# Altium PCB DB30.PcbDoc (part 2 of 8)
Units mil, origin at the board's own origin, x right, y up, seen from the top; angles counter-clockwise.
Board outline 3236.22 x 4456.69 mil, 8 copper layers (Top Layer, MidLayer1, MidLayer2, GND-Layer5, MidLayer3, VCC, MidLayer4, Bottom Layer), stack 61.8 mil thick; 219 components, 472 nets, 1811 pads, 1561 vias.
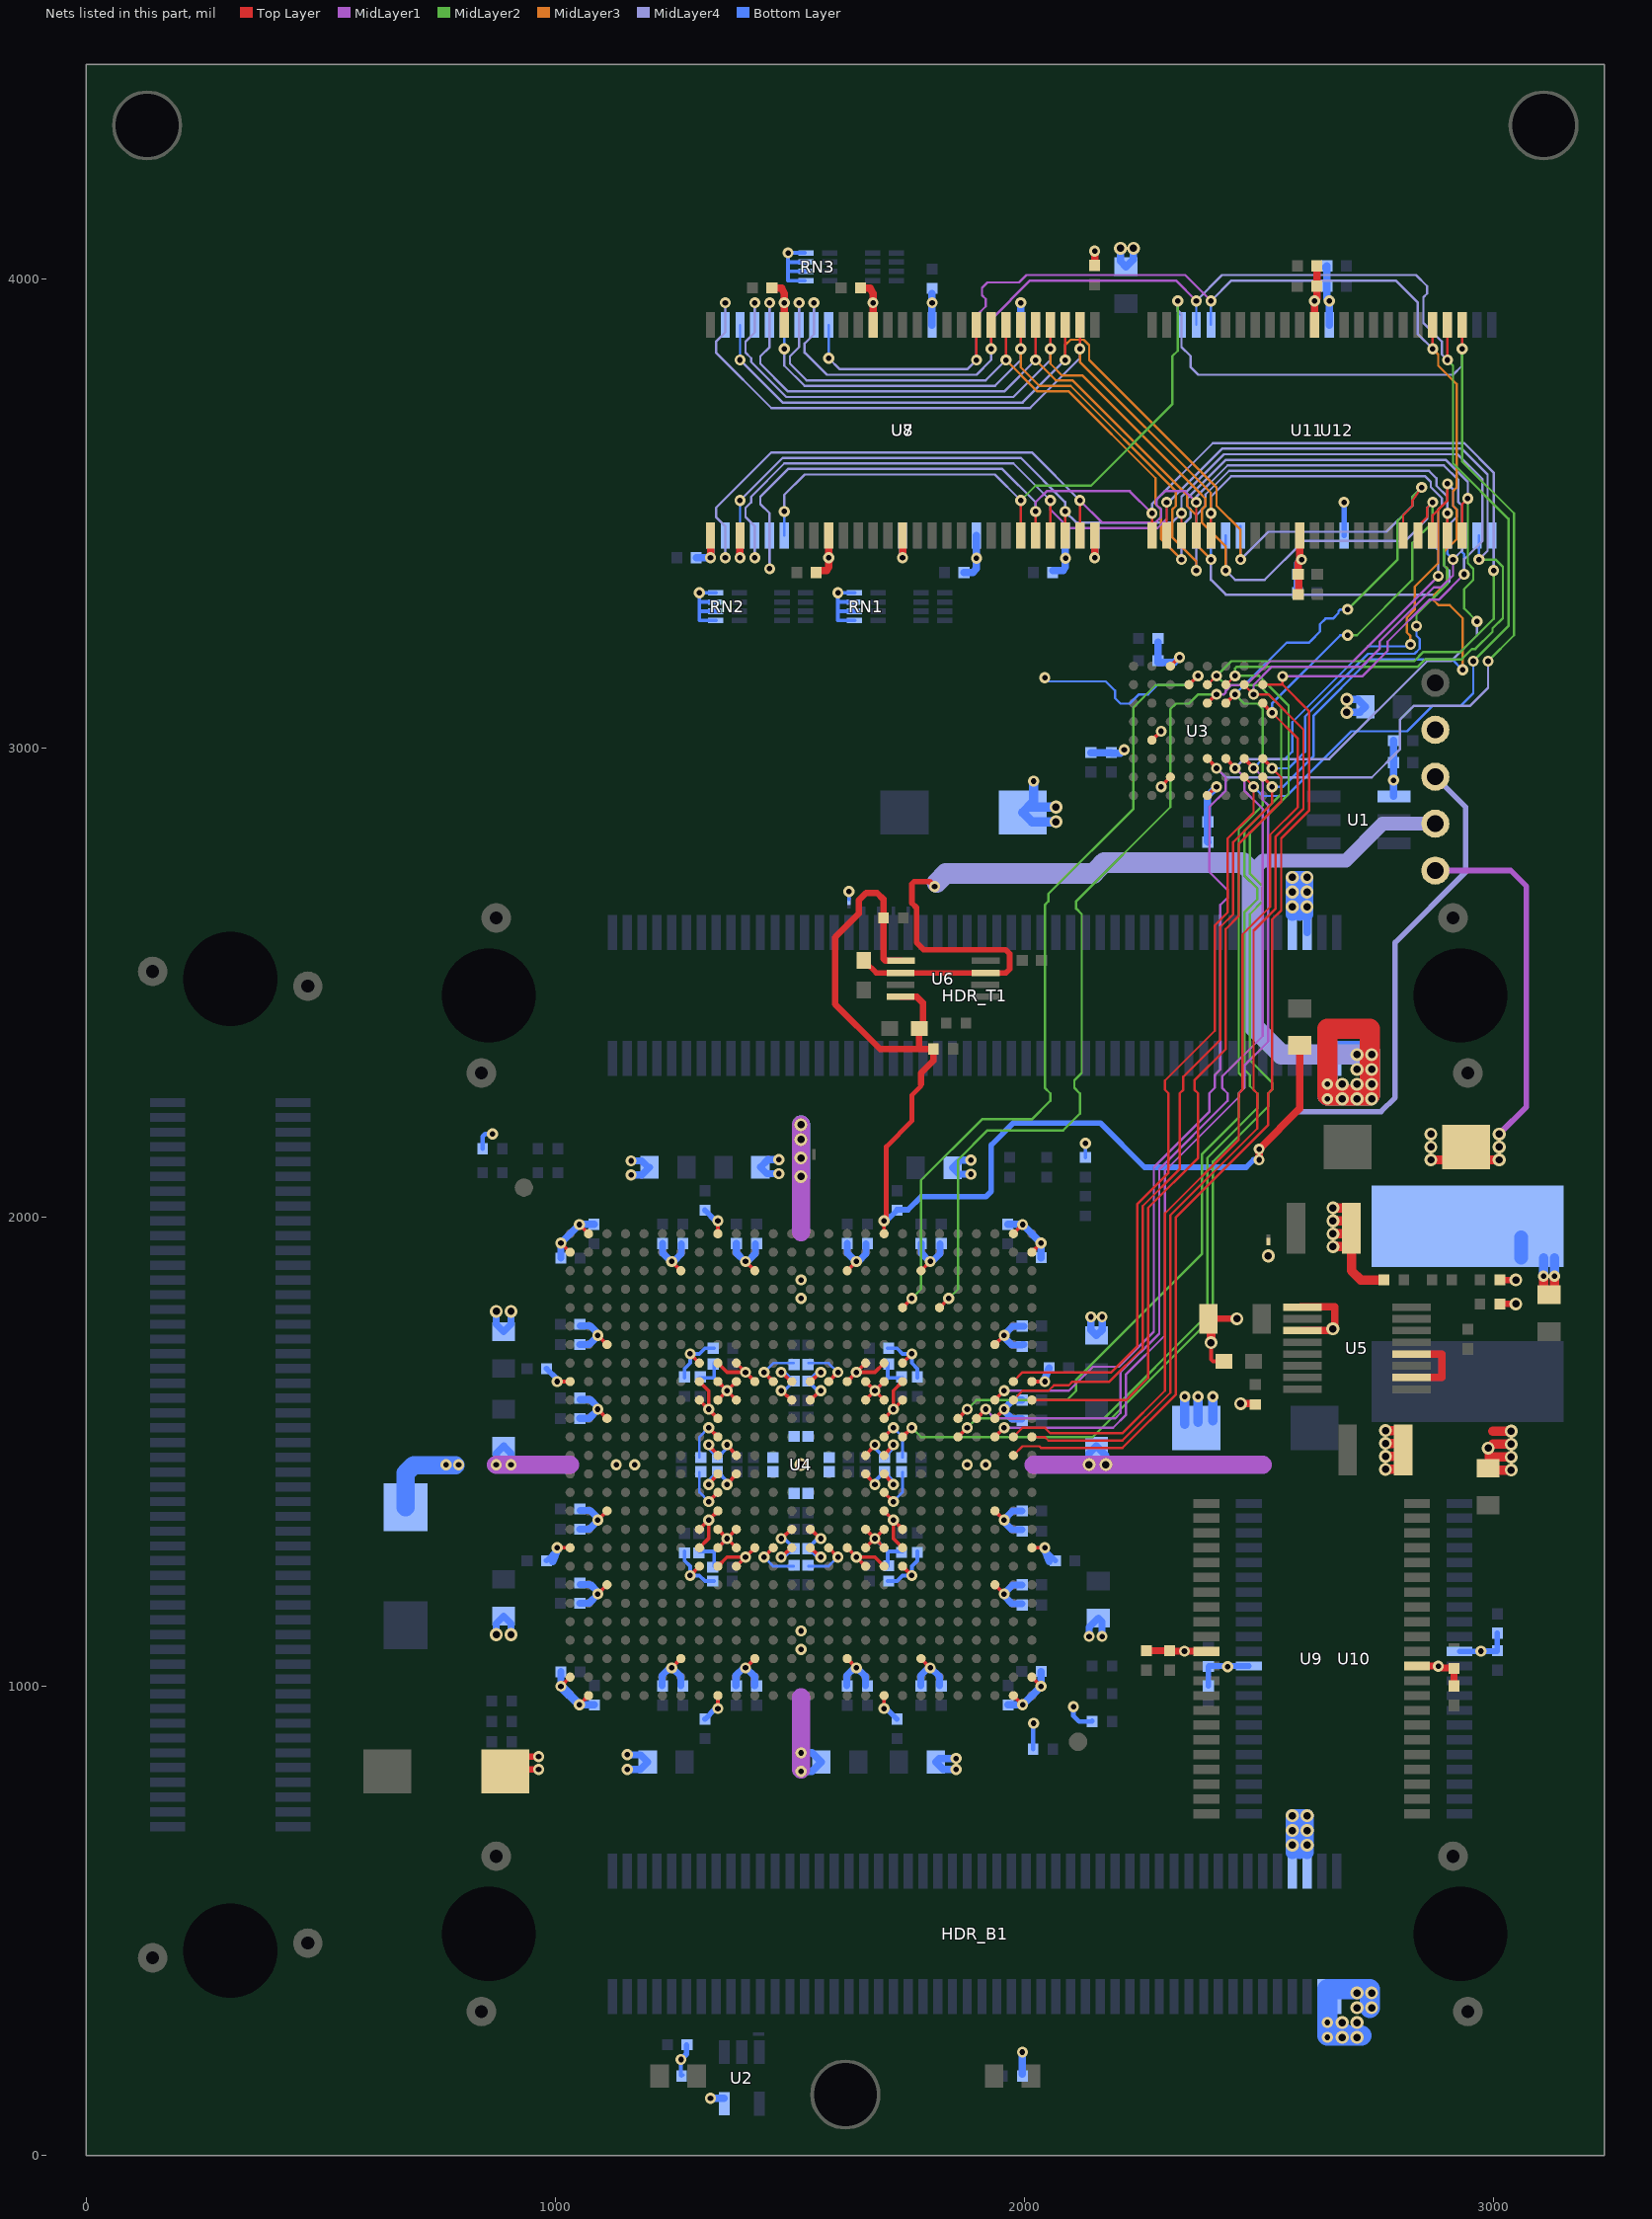
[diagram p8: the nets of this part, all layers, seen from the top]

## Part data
"Altium Logo Bot1" "Altium Logo Top1": library part D-000-0003, "Altium Logo for PCB"
C1 C7 C8 C9 C10 C11 C12 C13 C14 C26 C27 C28 C29 C30 C50 C51 C52 C53 C54 C55 C56 C57 C58 C59 C60 C61 C62 C63 C64 C65 C108 C109 C110 C114 C128 C129 C130 C131 C136 C137 C140 C141 C144 C145 C146 C147: library part D-101-0080, "Capacitor, Ceramic, 0.1uF 10% 16V 0402 (1005) X7R"
C2 C15 C16 C17 C18 C19 C20 C21 C22 C31 C32 C33 C34 C35 C36 C37 C38 C39 C40 C41 C66 C67 C68 C69 C70 C71 C72 C73 C74 C75 C76 C77 C78 C79 C80 C81 C82 C83 C84 C85 C86 C87 C88 C89 C90 C91 C92 C93 C94 C95 C96 C97 C98 C99 C100 C101 C102 C103 C104 C105 C111 C112 C113 C132 C133 C134 C135 C138 C139 C142 C143 C148 C149 C150 C151: library part D-101-0077, "Capacitor, Ceramic, 10nF 10% 16V 0402 (1005) X7R"
C3 C23 C106 C107 C119: library part D-101-0088, "Capacitor, Tantalum, 220uF 10% 10V MCCT-D (7343-31)"
C4 C5 C6 C24 C25 C42 C43 C44 C45 C46 C47 C48 C49 C115 C116 C120 C122: library part D-101-0087, "Capacitor, Ceramic, 10uF 10% 10V 0805 (2012) X5R"
C117: library part D-101-0069, "Capacitor, Ceramic, 470pF 5% 50V 0402 (1005) COG"
C118 C125 C126: library part D-101-0095, "Capacitor, Ceramic, 2.2uF 10% 10V 0603 (1608) X5R"
C121 C123: library part D-101-0021, "Capacitor, Ceramic, 22uF -20%/+80% 10V 1210 (3225) Y5V"
C124: library part D-101-0027, "Capacitor, Ceramic, 1uF 10% 25V 1206 (3216) X7R"
C127: library part D-101-0105, "Capacitor, Ceramic, 0.033uF 10% 10V 0402 (1005) X7R"
HDR_B1 HDR_L1 HDR_T1: library part D-300-0025, "Connector, Molex Docking Station 100 Pin Male 54075"
L1: library part D-102-0004, "Inductor, 2.2uH, 15A, 4R2, SMD"
LED1: library part D-153-0004, "LED, Green 0805 (2012) KP-2012SGD"
LED2: library part D-153-0003, "LED, Red 0805 (2013) HSMH-C170"
MH1 MH2 MH3: library part D-001-0001, "Mounting Hole, M3 Screw, Plated, Square Pad"
NT1 NT2 NT3 NT4 NT5 NT6 NT7 NT8: library part D-002-0002, "Net-Tie, Surface Mount, 2 x 0.4mm x 0.2mm SMT Pads - For 0.2mm Track"
R1 R2: library part D-100-0111, "Resistor, 270R 1% 0402 (1005)"
R3 R5 R9 R12: library part D-100-0088, "Resistor, 4K7 1% 0402 (1005)"
R4 R6 R7 R8 R10 R11 R13 R14 R15 R16 R17: library part D-100-0131, "Resistor, 100R 1% 0402 (1005)"
R18 R23 R24 R25: library part D-100-0132, "Resistor, 100K 1% 0402 (1005)"
R19: library part D-100-0128, "Resistor, 10R 1% 0402 (1005)"
R20 R22: library part D-100-0105, "Resistor, 2K7 1% 0402 (1005)"
R21: library part D-100-0109, "Resistor, 27K 1% 0402 (1005)"
RN1 RN2 RN3 RN4 RN5 RN6: library part D-104-0001, "Resistor Network, Isolated, 4 x 100R, 5%, SMD 0402 x 4"
TP1 TP2 TP3 TP4 TP5: library part D-006-0000, "Test Point, PCB Mount with Silkscreen Box"
U1: library part D-263-0002, "Dual Addressable Switch Plus 1KB Memory"
U2: library part D-205-0001, "SN74LVC1G04DBV, Single Inverter Gate, 1.65-V to 5.5-V"
U3: library part D-262-0001, "S29GL256N11FFIV10, 256 Megabit (16M x 16) 3.0V Page Mode Flash Memory"
U4: library part D-241-0001, "FPGA, Xilinx Spartan3-1500 FG676 Speed=4"
U5: library part D-204-0002, "MAX1831EEE, 3A, 1MHz, Low-Voltage, Step-Down Regulators with Synchronous Rectification and Internal Switches"
U6: library part D-204-0016, "MAX8860EUA18+, 1.8V Linear Regulator with adjustable Output, Low-noise, Low-dropout, 300mA, uMAX"
U7 U8: library part D-261-0000, "MT48LC16M16A2TG, 256 Mbit High-Speed CMOS SDRAM, 16Mb x 16Bit x 4 Banks, TSOP54"
U9 U10 U11 U12: library part D-260-0000, "K6R4016V1D-TC10T, 256K x 16-Bit SRAM, TSOP44"

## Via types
v1: diameter 23.62, hole 11.81, Top Layer to Bottom Layer, 944 vias
v2: diameter 23.62, hole 11.81, Top Layer to Bottom Layer, tented both sides, 477 vias
v3: diameter 27.56, hole 15.75, Top Layer to Bottom Layer, 139 vias
v4: diameter 23.62, hole 11.81, Top Layer to Bottom Layer, tented top, 1 vias

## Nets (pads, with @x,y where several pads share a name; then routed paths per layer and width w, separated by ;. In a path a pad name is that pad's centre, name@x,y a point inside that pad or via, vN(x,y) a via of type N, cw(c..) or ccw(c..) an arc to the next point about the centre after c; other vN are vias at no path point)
1V2: C3.1 C4.1 C5.1 C6.1 C7.1 C8.1 C9.1 C10.1 C11.1 C12.1 C13.1 C14.1 C15.1 C16.1 C17.1 C18.1 C19.1 C20.1 C21.1 C22.1 C119.1 C122.1 C123.1 L1.2 R20.1 TP5.1 U4.H8 U4.H19 U4.J9 U4.J10 U4.J17 U4.J18 U4.K9 U4.K10 U4.K17 U4.K18 U4.U9 U4.U10 U4.U17 U4.U18 U4.V9 U4.V10 U4.V17 U4.V18 U4.W8 U4.W19 | length 4494.8
  Top Layer w7.87: v1(1287.4,1236.22) U4.W8@1307.09,1255.91 ; v1(1287.4,1708.66) U4.H8@1307.09,1688.98 ; U4.V9@1346.46,1295.28 v1(1366.14,1314.96) ; U4.U9@1346.46,1334.65 v1(1366.14,1314.96) ; U4.K9@1346.46,1610.24 v1(1366.14,1629.92) ; U4.J9@1346.46,1649.61 v1(1366.14,1629.92) ; U4.V10@1385.83,1295.28 v1(1366.14,1314.96) ; U4.U10@1385.83,1334.65 v1(1366.14,1314.96) ; U4.K10@1385.83,1610.24 v1(1366.14,1629.92) ; U4.J10@1385.83,1649.61 v1(1366.14,1629.92) ; U4.V17@1661.42,1295.28 v1(1681.1,1314.96) ; U4.U17@1661.42,1334.65 v1(1681.1,1314.96) ; U4.K17@1661.42,1610.24 v1(1681.1,1629.92) ; U4.J17@1661.42,1649.61 v1(1681.1,1629.92) ; U4.V18@1700.79,1295.28 v1(1681.1,1314.96) ; U4.U18@1700.79,1334.65 v1(1681.1,1314.96) ; U4.K18@1700.79,1610.24 v1(1681.1,1629.92) ; U4.J18@1700.79,1649.61 v1(1681.1,1629.92) ; U4.W19@1740.16,1255.91 v1(1759.84,1236.22) ; U4.H19@1740.16,1688.98 v1(1759.84,1708.66)
  Top Layer w19.68: C123.1@2694.88,1974.41 2692.91,1976.37 C123.1@2704.72,1988.19 ; C123.1@2696.85,1948.82 2696.85,1976.37 2696.85,1885.83 2716.54,1866.14 R20.1@2766.21,1866.14 ; v3(2866.14,2122.05) C119.1@2913.39,2122.05 ; C119.1@2941.3,2122.05 v3(3011.81,2122.05) ; C119.1@2941.3,2149.61 C119.1@2941.02,2149.33 C119.1@2968.3,2122.05 ; C122.1@3106.3,1834.65 v1(3106.3,1874.02) ; C122.1@3129.92,1834.65 v1(3129.92,1874.02)
  Top Layer w20: v3(2657.47,1937) C123.1@2696.85,1937 ; v3(2657.47,1964.56) C123.1@2696.85,1964.56 ; v3(2657.47,1992.12) C123.1@2696.85,1992.12 ; v3(2657.47,2019.68) C123.1@2696.85,2019.68
  MidLayer1 w12: TP5.1@2875.71,2738.67 3036.33,2738.67 3070,2705 3070,2235.35 v3(3011.81,2177.17)
  MidLayer1 w39.37: v1(874.02,1472.44) 1031.5,1472.44 ; v1@1523.62,822.83 1523.62,976.38 ; 1523.62,1968.5 v3(1523.62,2196.85) ; 2019.68,1472.44 v3(2137.8,1472.44) 2507.87,1472.44
  Bottom Layer w7.87: C19.1@1275.59,1287.4 1275.59,1267.72 1287.4,1255.91 v1(1287.4,1236.22) 1307.09,1236.22 1318.9,1224.41 C20.1@1338.58,1224.41 ; C13.1@1275.59,1657.48 1275.59,1677.17 1287.4,1688.98 v1(1287.4,1708.66) 1307.09,1708.66 1318.9,1720.47 C18.1@1338.58,1720.47 ; C11.1@1307.08,1287.4 1338.58,1287.4 ; C22.1@1307.09,1657.48 1338.58,1657.48 ; C9.1@1338.58,1255.9 1338.58,1287.4 ; C14.1@1338.58,1688.98 1338.58,1657.48 ; v1(1366.14,1314.96) 1338.58,1287.4 ; v1(1366.14,1629.92) 1338.58,1657.48 ; v1(1681.1,1314.96) 1708.66,1287.4 ; v1(1681.1,1629.92) 1708.66,1657.48 ; C15.1@1708.66,1224.41 1728.35,1224.41 1740.16,1236.22 v1(1759.84,1236.22) 1759.84,1255.9 1771.65,1267.72 C8.1@1771.65,1287.4 ; C7.1@1708.66,1255.9 1708.66,1287.4 ; C12.1@1708.66,1688.98 1708.66,1657.48 ; C21.1@1708.66,1720.47 1728.35,1720.47 1740.16,1708.66 v1(1759.84,1708.66) 1759.84,1688.98 1771.65,1677.17 C10.1@1771.65,1657.48 ; C16.1@1740.16,1287.4 1708.66,1287.4 ; C17.1@1740.16,1657.48 1708.66,1657.48
  Bottom Layer w15.75: v1(874.02,1472.44) 874.02,1496.06 C4.1@889.76,1511.81 905.51,1496.06 v1(905.51,1472.44) ; v1(1523.62,818.9) 1547.24,818.9 C5.1@1566.93,838.58 1547.24,858.27 v1(1523.62,858.27) ; v3(2137.8,1472.44) 2137.8,1496.06 C6.1@2153.54,1511.81 2173.23,1492.12 v3(2173.23,1472.44)
  Bottom Layer w19.68: v1(3106.3,1874.02) L1.2@3106.3,1913.39 ; v1(3129.92,1874.02) L1.2@3129.92,1913.39
  Bottom Layer w20: C3.1@2341.79,1558.51 v1(2341.79,1617.56) ; C3.1@2370.08,1562.45 v1(2370.08,1617.56) ; C3.1@2401.58,1566.38 v1(2401.58,1617.56)
  Bottom Layer w29.53: L1.2@3059.06,1913.38 L1.2@3059.06,1956.69
  Bottom Layer w39.37: v3(1523.62,2086.61) v3(1523.62,2196.85)
  other v1: 1523.62,1078.74 1523.62,1118.11 1129.92,1472.44 1169.29,1472.44 1877.95,1472.44 1917.32,1472.44 1523.62,1826.77 1523.62,1866.14
  other v3: 1523.62,2125.98 2866.14,2149.61 3011.81,2149.61 1523.62,2165.35 2866.14,2177.17
2V5: C23.1 C24.1 C25.1 C26.1 C27.1 C28.1 C29.1 C30.1 C31.1 C32.1 C33.1 C34.1 C35.1 C36.1 C37.1 C38.1 C39.1 C40.1 C41.1 C125.1 R18.2 R24.1 TP3.1 U4.A2 U4.A9 U4.A18 U4.A25 U4.AE1 U4.AE26 U4.AF2 U4.AF9 U4.AF18 U4.AF25 U4.B1 U4.B26 U4.J1 U4.J26 U4.V1 U4.V26 U6.1 U6.4 | length 5138.7
  Top Layer w5: 1779.53,2279.53 1779.53,2283.46
  Top Layer w7.87: v1(1003.94,1295.28) U4.V1@1031.5,1295.28 ; v1(1003.94,1649.61) U4.J1@1031.5,1649.61 ; v1(1011.81,1000) U4.AE1@1031.5,1019.68 ; v1(1011.81,1944.88) U4.B1@1031.5,1925.2 ; v1(1051.18,960.63) U4.AF2@1070.87,980.31 ; v1(1051.18,1984.25) U4.A2@1070.87,1964.57 ; v1(1346.46,952.76) U4.AF9@1346.46,980.31 ; U4.A9@1346.46,1964.57 v1(1346.46,1992.13) ; v1(1700.79,952.76) U4.AF18@1700.79,980.31 ; U4.A18@1700.79,1964.57 v1(1700.79,1992.13) ; U4.AF25@1976.38,980.31 v1(1996.06,960.63) ; U4.A25@1976.38,1964.57 v1(1996.06,1984.25) ; U4.AE26@2015.75,1019.68 v1(2035.43,1000) ; U4.V26@2015.75,1295.28 v1(2043.31,1295.28) ; U4.J26@2015.75,1649.61 v1(2043.31,1649.61) ; U4.B26@2015.75,1925.2 v1(2035.43,1944.88)
  Top Layer w10: v1(1700.79,1992.13) 1705.41,1996.75 1705.41,2150.3 1759.84,2204.72 1759.84,2236.22 1759.84,2259.84 1779.53,2279.53
  Top Layer w13.78: C23.1@893.78,818.62 925.55,850.39 v1(964.57,850.39) ; C23.1@897.99,822.83 v1(964.57,822.83) ; U6.4@1736.22,2469.48 1770.67,2469.48 1783.46,2456.69 1783.46,2413.39 C125.1@1775.59,2405.51 ; U6.1@1737.2,2546.25 1703.75,2546.25 1699.29,2550.71 R24.1@1699.29,2637.79 1699.29,2677.68 1686.02,2690.94 1662.4,2690.94 1646.65,2675.2 1646.65,2646.65 1596.46,2596.46 1596.46,2453.74 1691.93,2358.26 R18.2@1805.59,2358.26 ; 1775.59,2358.27 C125.1@1775.59,2401.57 ; 1779.53,2283.46 1779.53,2307.09 1795.28,2322.83 1805.59,2333.15 R18.2@1805.59,2354.33
  Top Layer w15.75: v1@2500,2125.97 v1(2500,2145) 2586.61,2231.61 2586.61,2267.72 C24.1@2586.61,2366.14
  MidLayer4 w11.81: v1(2500,2122.05) v1(2500,2145) 2580,2225 2760,2225 2790,2255 2790,2585 2940,2735 2940,2874.37 TP3.1@2875.71,2938.67
  Bottom Layer w7.87: v1@1341.53,1992.13 v1(1346.46,1992.13)
  Bottom Layer w11.81: C28.1@981.3,1267.71 1003.94,1290.35 v1(1003.94,1295.28) ; C32.1@981.3,1677.16 1003.94,1654.52 v1(1003.94,1649.61) ; C40.1@1318.89,930.12 1341.53,952.76 v1(1346.46,952.76) ; C29.1@1318.89,2014.76 v1@1341.53,1992.13 ; v1(1700.79,952.76) 1705.7,952.76 C30.1@1728.34,930.12 ; v1(1700.79,1992.13) 1705.71,1992.13 C26.1@1728.34,2014.76 ; C26.1@1728.34,2015.74 1751.97,2015.74 1779.52,2043.3 1917.32,2043.3 1929.13,2055.11 1929.13,2153.54 1976.37,2200.78 2161.41,2200.78 2255.9,2106.29 2472.44,2106.29 2488.18,2122.04 v1(2500,2122.05) ; v1(2043.31,1295.28) 2043.31,1290.35 C39.1@2065.94,1267.71
  Bottom Layer w15.75: 994.63,1266.18 v1@1003.94,1290.35 ; v1(1011.81,1000) 1011.81,1030.92 C35.1@1011.81,1031.49 ; C41.1@1011.81,1913.39 v1(1011.81,1944.88) v1(1051.18,1984.25) 1082.1,1984.25 C33.1@1082.68,1984.25 ; v1(1051.18,960.63) C38.1@1082.68,960.63 ; v1(1476.26,2092.6) 1450.71,2092.6 C25.1@1437.01,2106.29 1453.31,2122.6 v1(1476.26,2122.6) ; C31.1@1964.57,960.63 1965.14,960.63 v1(1996.06,960.63) v1(2035.43,1000) C36.1@2035.43,1031.5 ; C34.1@1964.57,1984.25 v1(1996.06,1984.25) v1(2035.43,1944.88) 2035.43,1913.96 C37.1@2035.43,1913.39 ; v1@2042.32,1650.59 v1(2043.31,1649.61) 2043.31,1654.53 C27.1@2052.62,1678.7 ; v1@2043.31,1290.35 2052.62,1266.18
  Bottom Layer w19.68: v1(1011.81,1000) v1(1051.18,960.63)
3V3: C1.2 C2.1 C42.1 C43.1 C44.1 C45.1 C46.1 C47.1 C48.1 C49.1 C50.1 C51.1 C52.1 C53.1 C54.1 C55.1 C56.1 C57.1 C58.1 C59.1 C60.1 C61.1 C62.1 C63.1 C64.1 C65.1 C66.1 C67.1 C68.1 C69.1 C70.1 C71.1 C72.1 C73.1 C74.1 C75.1 C76.1 C77.1 C78.1 C79.1 C80.1 C81.1 C82.1 C83.1 C84.1 C85.1 C86.1 C87.1 C88.1 C89.1 C90.1 C91.1 C92.1 C93.1 C94.1 C95.1 C96.1 C97.1 C98.1 C99.1 C100.1 C101.1 C102.1 C103.1 C104.1 C105.1 C106.1 C107.1 C108.2 C109.1 C110.1 C111.1 C112.1 C113.1 C114.1 C115.1 C116.1 C128.1 C129.1 C130.1 C131.1 C132.1 C133.1 C134.1 C135.1 C136.1 C137.1 C138.1 C139.1 C140.1 C141.1 C142.1 C143.1 C144.1 C145.1 C146.1 C147.1 C148.1 C149.1 C150.1 C151.1 HDR_B1.94 HDR_B1.96 HDR_T1.94 HDR_T1.96 NT1.2 R1.1 R2.1 R3.2 R5.2 R9.2 R12.2 RN1.1 RN1.2 RN1.3 RN1.4 RN2.1 RN2.2 RN2.3 RN2.4 RN3.1 RN3.2 RN3.3 RN3.4 TP2.1 U1.4 U2.5 U3.D8 U3.F1 U3.F7 U3.G5 U4.AD7 U4.AD11 U4.AD16 U4.AD20 U4.C7 U4.C11 U4.C16 U4.C20 U4.G3 U4.G24 U4.H9 U4.H10 U4.H17 U4.H18 U4.J8 U4.J11 U4.J12 U4.J13 U4.J14 U4.J15 U4.J16 U4.J19 U4.K8 U4.K13 U4.K14 U4.K19 U4.L3 U4.L9 U4.L18 U4.L24 U4.M9 U4.M18 U4.N9 U4.N10 U4.N17 U4.N18 U4.P9 U4.P10 U4.P17 U4.P18 U4.R9 U4.R18 U4.T3 U4.T9 U4.T18 U4.T24 U4.U8 U4.U13 U4.U14 U4.U19 U4.V8 U4.V11 U4.V12 U4.V13 U4.V14 U4.V15 U4.V16 U4.V19 U4.W9 U4.W10 U4.W17 U4.W18 U4.Y3 U4.Y24 U7.1 U7.3 U7.9 U7.14 U7.27 U7.43 U7.49 U8.1 U8.3 U8.9 U8.14 U8.27 U8.43 U8.49 U9.11 U9.33 U10.11 U10.33 U11.11 U11.33 U12.11 U12.33 | length 10233.3
  Top Layer w5: U7.9@1582.68,3433.07 U7.9@1582.68,3452.76
  Top Layer w7.87: v1(1090.55,1196.85) U4.Y3@1110.24,1216.54 ; v1(1090.55,1354.33) U4.T3@1110.24,1374.02 ; v1(1090.55,1590.55) U4.L3@1110.24,1570.87 ; v1(1090.55,1748.03) U4.G3@1110.24,1728.35 ; v1(1248.03,1039.37) U4.AD7@1267.72,1059.05 ; v1(1248.03,1905.51) U4.C7@1267.72,1885.83 ; U4.V8@1307.09,1295.28 1326.77,1314.96 v1(1326.77,1354.33) ; U4.U8@1307.09,1334.65 v1(1326.77,1354.33) ; U4.K8@1307.09,1610.24 v1(1326.77,1590.55) ; U4.J8@1307.09,1649.61 1326.77,1629.92 v1(1326.77,1590.55) ; v1(1326.77,1393.7) U4.R9@1346.46,1413.39 ; v1(1326.77,1430.12) U4.P9@1346.46,1452.76 ; v1(1326.77,1514.76) U4.N9@1346.46,1492.13 ; v1(1326.77,1551.18) U4.M9@1346.46,1531.5 ; U4.W9@1346.46,1255.91 1366.14,1275.59 v1(1405.51,1275.59) ; U4.T9@1346.46,1374.02 v1(1326.77,1354.33) ; U4.L9@1346.46,1570.87 v1(1326.77,1590.55) ; U4.H9@1346.46,1688.98 1366.14,1669.29 v1(1405.51,1669.29) ; v1(1366.14,1430.12) U4.P10@1385.83,1452.76 ; v1(1366.14,1514.76) U4.N10@1385.83,1492.13 ; U4.W10@1385.83,1255.91 v1(1405.51,1275.59) ; U4.H10@1385.83,1688.98 v1(1405.51,1669.29) ; v1(1405.51,1039.37) U4.AD11@1425.2,1059.05 ; v1(1405.51,1905.51) U4.C11@1425.2,1885.83 ; U4.V11@1425.2,1295.28 v1(1405.51,1275.59) ; U4.J11@1425.2,1649.61 v1(1405.51,1669.29) ; v1(1444.88,1275.59) U4.V12@1464.57,1295.28 ; v1(1444.88,1669.29) U4.J12@1464.57,1649.61 ; v1(1481.3,1275.59) U4.V13@1503.94,1295.28 ; v1(1481.3,1314.96) U4.U13@1503.94,1334.65 ; v1(1481.3,1629.92) U4.K13@1503.94,1610.24 ; v1(1481.3,1669.29) U4.J13@1503.94,1649.61 ; U4.V14@1543.31,1295.28 v1(1565.94,1275.59) ; U4.U14@1543.31,1334.65 v1(1565.95,1314.96) ; U4.K14@1543.31,1610.24 v1(1565.95,1629.92) ; U4.J14@1543.31,1649.61 v1(1565.94,1669.29) ; U4.V15@1582.68,1295.28 v1(1602.36,1275.59) ; U4.J15@1582.68,1649.61 v1(1602.36,1669.29) ; U4.AD16@1622.05,1059.05 v1(1641.73,1039.37) ; U4.V16@1622.05,1295.28 v1(1641.73,1275.59) ; U4.J16@1622.05,1649.61 v1(1641.73,1669.29) ; U4.C16@1622.05,1885.83 v1(1641.73,1905.51) ; U4.W17@1661.42,1255.91 v1(1641.73,1275.59) ; U4.P17@1661.42,1452.76 v1(1681.1,1430.12) ; U4.N17@1661.42,1492.13 v1(1681.1,1514.76) ; U4.H17@1661.42,1688.98 v1(1641.73,1669.29) ; U4.W18@1700.79,1255.91 1681.1,1275.59 v1(1641.73,1275.59) ; U4.T18@1700.79,1374.02 v1(1720.47,1354.33) ; U4.R18@1700.79,1413.39 v1(1720.47,1393.7) ; U4.P18@1700.79,1452.76 v1(1720.47,1430.12) ; U4.N18@1700.79,1492.13 v1(1720.47,1514.76) ; U4.M18@1700.79,1531.5 v1(1720.47,1551.18) ; U4.L18@1700.79,1570.87 v1(1720.47,1590.55) ; U4.H18@1700.79,1688.98 1681.1,1669.29 v1(1641.73,1669.29) ; U4.V19@1740.16,1295.28 1720.47,1314.96 v1(1720.47,1354.33) ; U4.U19@1740.16,1334.65 v1(1720.47,1354.33) ; U4.K19@1740.16,1610.24 v1(1720.47,1590.55) ; U4.J19@1740.16,1649.61 1720.47,1629.92 v1(1720.47,1590.55) ; U4.AD20@1779.53,1059.05 v1(1799.21,1039.37) ; U4.C20@1779.53,1885.83 v1(1799.21,1905.51) ; U4.Y24@1937.01,1216.54 v1(1956.69,1196.85) ; U4.T24@1937.01,1374.02 v1(1956.69,1354.33) ; U4.L24@1937.01,1570.87 v1(1956.69,1590.55) ; U4.G24@1937.01,1728.35 v1(1956.69,1748.03) ; U3.G5@2271.65,3016.73 v1(2291.34,3035.43) ; v1@2291.34,2918.31 U3.F7@2311.02,2937.99 ; U3.F1@2311.02,3174.21 v1@2330.71,3193.9 ; U3.D8@2389.76,2898.62 v1@2409.45,2918.31
  Top Layer w15: C139.1@2259.84,1075.78 C137.1@2309.14,1075.78 2309.92,1075 2343,1075 2343.2,1074.8 U9.33@2387.89,1074.8 ; U9.11@2836.71,1043.3 2885.83,1043.3 2889.76,1039.37 2914.45,1039.37 C136.1@2915.44,1038.38 C138.1@2915.44,1000.97 ; v1@2881.7,1043.3 v1(2882,1043)
  Top Layer w15.75: v2@1330.71,3409.45 U7.1@1330.71,3452.76 ; v2(1393.7,3405.51) U7.3@1393.7,3452.76 ; C132.1@1461.61,3980.31 1482.28,3980.32 1488.19,3968.51 ; U7.49@1488.19,3901.57 v2(1488.19,3948.82) ; v2@1488.19,3944.88 1488.19,3964.57 ; C129.1@1556.1,3377.95 1578.74,3377.95 1582.68,3385.83 1582.68,3389.76 1583.46,3401.52 1583.58,3403.35 v2@1583.66,3404.53 ; U7.9@1582.68,3452.76 v2@1582.68,3409.45 ; C133.1@1650.59,3980.31 1671.26,3980.32 1677.17,3968.51 v2@1677.17,3944.88 ; U7.43@1677.17,3901.57 v2(1677.17,3948.82) ; v2(1740.16,3405.51) U7.14@1740.16,3452.76 ; v2(2149.6,3405.52) U7.27@2149.61,3452.76 ; C128.1@2149.6,4028.54 v2(2149.61,4059.06) ; C148.1@2582.4,3371.05 C148.1@2583.38,3370.07 2583.38,3394.4 v2(2590.55,3401.57) 2586.61,3405.51 U11.11@2586.61,3452.76 ; C144.1@2584.37,3329.71 2584.37,3370.07 C148.1@2584.34,3370.23 ; U11.33@2618.11,3901.57 v2(2618.11,3952.76) 2623.03,3957.67 C145.1@2623.03,4027.55 ; v2@1582.68,3409.45 v2@1583.43,3405.66 ; v2@1582.68,3409.45 v2@1583.43,3405.66 ; v2@1583.43,3405.66 v2@1583.66,3404.53 ; v2@1583.43,3405.66 v2@1583.66,3404.53
  MidLayer4 w5: v3(2570.87,661.42) v3@2570.87,665.36
  Bottom Layer w5.51: C81.1@1307.09,1456.69 1307.09,1413.39 v1(1326.77,1393.7) ; C79.1@1307.09,1488.19 1307.09,1531.5 v1(1326.77,1551.18) ; v1(1444.88,1275.59) 1464.57,1255.91 C86.1@1507.87,1255.91 ; v1(1444.88,1669.29) 1464.57,1688.98 C80.1@1507.87,1688.98 ; C87.1@1539.37,1255.91 1582.68,1255.91 v1(1602.36,1275.59) ; C97.1@1539.37,1688.98 1582.68,1688.98 v1(1602.36,1669.29) ; v1(1720.47,1393.7) 1740.16,1413.39 C76.1@1740.16,1456.69 ; v1(1720.47,1551.18) 1740.16,1531.5 C96.1@1740.16,1488.19
  Bottom Layer w7.87: v1@865.98,2177.17 v1@865.98,2178 ; v1(1267.72,204.72) 1267.72,170.78 R1.1@1269.21,169.29 R1.1@1271.65,171.73 ; C108.2@1279.53,235.24 C108.2@1280.51,236.22 ; 1307.09,3291.34 RN2.2@1342.51,3291.34 ; 1307.09,3311.02 RN2.3@1342.51,3311.02 ; v1(1326.77,1430.12) 1326.77,1437.01 1346.46,1456.69 1366.14,1437.01 v1(1366.14,1430.12) ; v1@1326.77,1511.81 1326.77,1507.87 1346.46,1488.19 1366.14,1507.87 v1(1366.14,1514.76) ; RN2.1@1342.51,3271.65 1307.09,3271.65 v1(1307.09,3330.71) RN2.4@1342.51,3330.71 ; U2.5@1359.25,122.05 U2.5@1360.23,123.03 ; v1(1481.3,1275.59) 1488.19,1275.59 1507.38,1294.78 1507.87,1295.28 1488.19,1314.96 v1(1481.3,1314.96) ; v1(1481.3,1629.92) 1488.19,1629.92 1507.87,1649.61 1488.19,1669.29 v1(1481.3,1669.29) ; 1496.07,4015.74 RN3.2@1531.49,4015.74 ; 1496.07,4035.43 RN3.3@1531.49,4035.43 ; RN3.1@1531.49,3996.06 1496.07,3996.06 v1(1496.07,4055.11) RN3.4@1531.49,4055.11 ; v1@1559.06,1275.59 1539.86,1294.78 1539.37,1295.28 1559.05,1314.96 v1(1565.95,1314.96) ; v1(1565.95,1629.92) 1559.05,1629.92 1539.37,1649.61 1559.06,1669.29 v1(1565.94,1669.29) ; 1602.36,3291.34 RN1.2@1637.79,3291.34 ; 1602.36,3311.02 RN1.3@1637.79,3311.02 ; NT1.2@1625.98,2677.17 v2@1625.98,2688.98 ; RN1.1@1637.79,3271.65 1602.36,3271.65 v1(1602.36,3330.71) RN1.4@1637.79,3330.71 ; v1(1681.1,1430.12) 1681.1,1437.01 1700.79,1456.69 1703.09,1454.39 1720.47,1437.01 v1(1720.47,1430.12) ; v1(1681.1,1514.76) 1681.1,1507.87 1700.79,1488.19 1703.09,1490.49 1720.47,1507.87 v1(1720.47,1514.76) ; v1(1854.33,846.46) v1@1854.33,854.33 ; R5.2@2129.92,2127.48 v1(2129.92,2157.48) v1@2129.92,2161.42
  Bottom Layer w9.84: R3.2@844.96,2145.66 844.96,2171.73 850.39,2177.17 v1@865.98,2177.17 ; R9.2@2018.18,866.14 2018.18,915.82 v1(2019.68,921.26) ; v1(2104.33,956.69) 2104.33,937.01 2116.14,925.2 R12.2@2144.17,925.2 R12.2@2144.17,926.69
  Bottom Layer w11.81: v1(1267.72,204.72) 1279.53,216.54 C108.2@1279.53,235.24 ; C140.1@2391.82,1000.97 C142.1@2391.82,1042.31 2392.81,1043.3 U10.11@2478.44,1043.3 ; v1(2433,1042) v1@2434.3,1043.3 ; U12.11@2681.1,3452.76 v2(2681.1,3523.62) ; U10.33@2927.25,1074.79 2972.79,1074.79 v1(2973,1075) 3007.08,1075 C143.1@3007.87,1075.79 C141.1@3007.87,1113.19
  Bottom Layer w15: v3(874.02,1110.24) 874.02,1133.86 C45.1@889.76,1149.6 905.51,1133.85 v3(905.51,1110.24) ; v3(874.02,1799.21) 874.02,1771.65 C43.1@889.76,1755.9 905.51,1771.65 v3(905.51,1799.21) ; C84.1@1052.4,1177.16 1052.4,1177.4 1072.24,1177.4 v1@1090.55,1195.71 ; C53.1@1052.4,1334.88 1072.24,1334.88 v1@1090.55,1353.19 ; C58.1@1052.4,1571.1 1072.24,1571.1 v1@1090.55,1589.41 ; C61.1@1052.4,1728.58 1072.24,1728.58 v1@1090.55,1746.89 ; C56.1@1053.04,1217.4 1074.24,1217.4 1090.55,1201.1 v1(1090.55,1196.85) ; C101.1@1053.04,1374.88 1074.24,1374.88 1090.55,1358.58 v1(1090.55,1354.33) ; C102.1@1053.04,1611.1 1074.24,1611.1 1090.55,1594.8 v1(1090.55,1590.55) ; C104.1@1053.04,1768.58 1074.24,1768.58 1090.55,1752.28 v1(1090.55,1748.03) ; v2(1153.54,822.83) 1181.1,822.83 C49.1@1196.85,838.58 1181.1,854.33 v2(1153.54,854.33) ; v1(1161.54,2090) 1184.49,2090 C42.1@1200.78,2106.29 ; v1(1161.54,2120) 1184,2120 C42.1@1197,2107 ; C62.1@1227.48,1001.86 1227.48,1023.06 1243.78,1039.37 v1(1248.03,1039.37) ; C59.1@1228.58,1943.66 1228.58,1923.82 v1@1246.89,1905.51 ; v1(1248.03,1905.51) 1252.28,1905.51 1268.58,1921.82 C70.1@1268.58,1943.03 ; v1@1249.17,1039.37 1267.48,1021.06 C85.1@1267.48,1001.22 ; C83.1@1384.96,1001.86 1384.96,1023.06 1401.26,1039.37 v1(1405.51,1039.37) ; C100.1@1386.06,1943.66 1386.06,1923.82 v1@1404.37,1905.51 ; v1(1405.51,1905.51) 1409.76,1905.51 1426.06,1921.82 C65.1@1426.06,1943.02 ; v1@1406.65,1039.37 1424.96,1021.06 C57.1@1424.96,1001.22 ; C52.1@1621.18,1001.86 1621.18,1023.06 1637.49,1039.37 v1(1641.73,1039.37) ; C99.1@1622.29,1943.66 1622.29,1923.82 v1@1640.59,1905.51 ; v1(1641.73,1905.51) 1645.98,1905.51 1662.29,1921.82 C64.1@1662.29,1943.02 ; v1@1642.88,1039.37 1661.18,1021.06 C91.1@1661.18,1001.22 ; C51.1@1778.66,1001.86 1778.66,1023.06 1794.97,1039.37 v1(1799.21,1039.37) ; C68.1@1779.77,1943.66 1779.77,1923.82 v1@1798.07,1905.51 ; v1(1799.21,1905.51) 1803.46,1905.51 1819.77,1921.82 C60.1@1819.77,1943.02 ; v1@1800.36,1039.37 1818.66,1021.06 C69.1@1818.66,1001.22 ; C48.1@1811.02,838.58 1826.77,822.83 v1(1854.33,822.83) ; v1(1885.83,2091.61) 1860.28,2091.6 C44.1@1846.58,2105.29 1862.88,2121.6 v1(1885.83,2121.61) ; v1(1956.69,1196.85) 1956.69,1192.6 1973,1176.3 C50.1@1994.21,1176.3 ; v1@1956.69,1197.99 1975,1216.3 C103.1@1994.84,1216.3 ; v1(1956.69,1354.33) 1956.69,1350.08 1973,1333.78 C105.1@1994.21,1333.78 ; v1@1956.69,1355.47 1975,1373.78 C55.1@1994.84,1373.78 ; v1(1956.69,1590.55) 1956.69,1586.31 1973,1570 C63.1@1994.21,1570 ; v1@1956.69,1591.69 1975,1610 C71.1@1994.84,1610 ; v1(1956.69,1748.03) 1956.69,1743.79 1973,1727.48 C54.1@1994.21,1727.48 ; v1@1956.69,1749.17 1975,1767.48 1994.84,1767.48 C89.1@1994.84,1767.71 ; C54.1@1995.07,1728.35 C54.1@1999.01,1728.35 ; C89.1@1995.07,1767.71 C89.1@1999.01,1767.72 ; v1(2137.8,1106.3) 2137.8,1125.99 C47.1@2157.48,1145.67 2165.35,1137.79 v1(2165.35,1106.3)
  Bottom Layer w15.75: C130.1@1300.19,3405.5 v2(1330.71,3405.51) ; U8.27@1329.73,3437.99 U8.27@1330.71,3437.01 ; v1(1330.71,122.05) U2.5@1359.25,122.05 ; v2@1330.71,3404.53 U8.27@1330.71,3452.76 ; v2(1740.16,3405.51) U8.14@1740.16,3452.76 ; U8.43@1803.15,3901.57 C131.1@1803.15,3968.5 ; C48.1@1811.02,838.58 1818.9,846.46 v1(1854.33,846.46) ; C135.1@1871.06,3374.01 1889.76,3374.01 1897.64,3381.89 v2(1897.64,3404.53) 1897.64,3405.51 U8.9@1897.64,3452.76 ; U8.49@1992.13,3901.57 v2(1992.13,3948.82) ; R2.1@1995.59,173.23 v1(1995.59,220.47) ; C134.1@2060.05,3377.95 2082.68,3377.95 2086.62,3385.83 2086.62,3389.76 U8.3@2086.61,3452.76 ; v2@2086.62,3409.45 v2(2087.6,3404.53) ; v4(2141.73,1787.4) 2141.73,1759.83 C46.1@2153.54,1748.03 2165.35,1759.84 v1(2165.35,1787.4) ; C114.1@2141.73,2990.16 C111.1@2185.04,2990.16 2186.02,2989.18 2204.73,2989.18 v1(2212.6,2996.06) ; v2(2149.6,3405.52) 2149.61,3409.45 U8.1@2149.61,3452.76 ; v3(2204.72,4064.96) 2204.72,4037.4 C116.1@2216.53,4025.58 2232.28,4041.34 v3(2232.28,4064.96) ; C110.1@2284.45,3225.39 2284.45,3182.09 2318.9,3182.09 v1@2330.22,3193.41 ; C109.1@2390.74,2799.21 2389.76,2800.19 2389.76,2897.64 v1@2409.45,2917.33 ; C146.1@2581.69,3330.7 C150.1@2581.69,3370.07 2582.68,3371.06 2582.68,3393.7 v2(2590.55,3401.57) ; HDR_T1.96@2602.36,2606.3 2602.36,2645.67 ; C147.1@2641.73,4024.61 C147.1@2644.68,4027.55 2644.68,3957.68 v2(2649.61,3952.76) v2@2649.61,3956.7 ; U12.33@2649.88,3901.57 v2@2649.88,3944.88 ; v3(2687.01,3075.79) 2714.58,3075.79 C115.1@2726.38,3087.59 2710.63,3103.35 v3(2687.01,3103.35) ; U1.4@2786.42,2897.63 C1.2@2786.41,3015.74
  Bottom Layer w19.68: C107.1@2007.68,2874.02 v3(2066.93,2874.02) ; v1(2019.68,2929.13) 2019.68,2886.02 C107.1@1996.14,2862.47 2016.09,2842.52 v3(2066.93,2842.52)
  Bottom Layer w27.56: 2570.87,645.67 v3(2570.87,661.42) v3(2570.87,692.91) v3(2570.87,724.41) v3(2602.37,724.41) v3(2602.37,692.91) v3(2602.37,661.42) 2602.36,645.67 ; 2570.87,2645.67 v3(2570.87,2724.41) v3(2602.36,2724.41) 2602.36,2645.67 ; 2586.62,645.67 2586.62,724.41 ; 2586.61,2645.67 2586.61,2724.41
  Bottom Layer w39.37: C106.1@681.1,1381.89 681.1,1454.1 698,1471 v1@787.32,1471
  other v1: 2341,1075 767.24,1472.44 794.02,1472.44 866.14,2177.17 2291.34,2917.32 2409.45,2917.32 2330.71,3192.91
  other v2: 1625.98,2693.9 2786.42,2931.1 1582.68,3405.51 1803.15,3948.82
  other v3: 1523.62,1472.44 2570.87,2661.42 2602.36,2661.42 2570.87,2692.91 2602.36,2692.91
5V0: C120.1 C121.1 C126.1 HDR_B1.97 HDR_B1.99 HDR_T1.97 HDR_T1.99 R19.1 TP4.1 U5.2 U5.4 U6.2 U6.7 | length 4216.9
  Top Layer w12: C126.1@1661.42,2543.31 1684.06,2520.66 1951.78,2520.66 1960.66,2520.66 1968.5,2528.5 1968.5,2537.39 1968.5,2555 1968.5,2561.5 1960,2570 1953.5,2570 1785,2570 1770,2585 1770,2659.13 ; 1760,2669.13 1770,2659.13 ; 1760,2669.13 1760,2710 1765,2715 1798.1,2715 ; 1760,2669.13 1770,2659.13 ; 1798.1,2715 v2(1808.5,2704.6) 1798.1,2715
  Top Layer w15.75: v3(2460.63,1602.36) 2490.62,1602.36 R19.1@2492.12,1600.86 ; U5.2@2824.58,1658.25 2889.67,1658.25 2889.67,1708.25 U5.4@2824.58,1708.25 ; C120.1@2988.18,1464.56 v3(2988.19,1507.87)
  Top Layer w20: v3(2769.67,1517.71) C121.1@2809.04,1517.71 ; v3(2769.67,1545.27) C121.1@2809.04,1545.27 ; v3(2769.67,1462.59) C121.1@2809.04,1462.59 ; v3(2769.67,1490.15) C121.1@2809.04,1490.15 ; C120.1@2998.04,1461.1 v3(3037.41,1461.1) ; 2998.04,1488.66 v3(3037.41,1488.66) ; v3@2998.04,1516.22 v3(3037.41,1516.22) ; 2998.04,1543.78 v3(3037.41,1543.78)
  Top Layer w43.31: v1@2645.67,2259.84 2645.67,2401.58 2736.22,2401.58 2736.22,2259.84 v1@2645.67,2259.84
  MidLayer4 w30: 2484.5,2736.3 2508.2,2760 2685,2760 2763.67,2838.67 TP4.1@2875.71,2838.67
  MidLayer4 w43.31: v2@1813.28,2713.28 1832.4,2732.4 1965.4,2732.4 2146.5,2732.4 2156.3,2742.2 2169.6,2755.5 2465.3,2755.5 2484.5,2736.3 2484.5,2409.8 2547.84,2346.46 v3(2708.66,2346.46)
  Bottom Layer w43.31: 2649.61,263.78 v3@2677.17,263.78 ; v3@2716.54,255.91 2718.5,255.91 2708.66,255.91 2677.17,255.9 2645.67,255.9 2645.67,354.33 2736.22,354.33 2736.22,346.46 v3@2736.22,314.96 ; v1@2645.67,2259.84 2645.67,2354.33 2736.22,2354.33 2736.22,2346.46 2736.22,2314.96 2736.22,2283.47 2736.22,2259.84 v1@2645.67,2259.84
  other v1: 2645.67,251.97 2645.67,283.46 2645.67,2251.97 2645.67,2283.47
  other v3: 2677.17,251.97 2708.66,251.97 2677.17,283.46 2708.66,283.46 2708.66,314.96 2740.16,314.96 2708.66,346.46 2740.16,346.46 2677.17,2251.97 2708.66,2251.97 2740.16,2251.97 2677.17,2283.47 2708.66,2283.47 2740.16,2283.47 2708.66,2314.96 2740.16,2314.96 2740.16,2346.46
AGND: C118.2 C124.1 NT8.1 R22.2 R23.2 U5.9 U5.11 | length 449.7
  Top Layer w7.87: v3(2397.64,1732.28) 2397.64,1696.85 2401.58,1692.91 C118.2@2425.19,1692.91
  Top Layer w13.78: C124.1@2391.73,1783.46 v3(2452.75,1783.46) ; R23.2@3013.3,1814.96 v3(3047.24,1814.96) ; R22.2@3013.3,1866.14 v3(3047.24,1866.14)
  Top Layer w15.75: U5.9@2589.19,1808.68 2591.08,1808.69 2592.58,1808.69 2661.35,1808.87 2661.35,1808.76 ; U5.11@2591.08,1758.25 U5.11@2592.58,1758.25 2653.67,1758.25 v3(2657.19,1761.76) ; 2657.48,1808.76 2661.35,1808.76 ; v3@2661.35,1758.26 2661.35,1761.76 2661.35,1808.76
  Top Layer w19.68: v3(2397.64,1732.28) 2397.64,1777.55 C124.1@2391.73,1783.46 C124.1@2397.64,1789.37
  other v3: 2519.68,1917.32
BUS_A1: U3.E2 U4.E19 | length 2131.4
  Top Layer w7.87: U4.E19@1740.16,1807.09 v1(1759.84,1826.77) ; U3.E2@2350.39,3134.84 v1(2370.08,3153.55)
  MidLayer2 w5: v1(1759.84,1826.77) 1779.53,1846.46 1779.53,2027.56 1779.53,2039.37 1779.53,2078.74 1909.45,2208.66 2015.75,2208.66 2055.12,2248.03 2055.12,2263.78 2043.31,2275.59 2043.31,2665.35 2051.18,2673.23 2051.18,2688.98 2232.28,2870.08 2232.28,3086.61 2279.53,3133.86 2350.39,3133.86 v1(2370.08,3153.55)
  Bottom Layer w5: v1(2043.31,3149.61) 2051.18,3141.73 2173.23,3141.73 2192.91,3122.05 2192.91,3106.3 2204.72,3094.49 2224.41,3094.49 2244.09,3114.17 2263.78,3114.17 2283.46,3133.86 2350.39,3133.86 v1(2370.08,3153.55)
BUS_A2: U3.D2 U4.M22 U7.23 U8.23 U11.1 U12.1 | length 5381.9
  Top Layer w5: U7.23@2023.62,3452.76 v2(2023.62,3503.93) ; U11.1@2271.65,3452.76 v1(2271.65,3500) ; U3.D2@2389.76,3134.84 2390.75,3134.85 v1(2409.45,3153.54)
  Top Layer w7.87: U4.M22@1858.27,1531.5 v1(1877.95,1551.18)
  MidLayer1 w5: v2(2023.62,3503.93) 2023.62,3523.62 2047.24,3547.24 2224.41,3547.24 v1(2271.65,3500)
  MidLayer2 w5: v1(1877.95,1551.18) 1897.64,1570.87 2082.68,1570.87 2090.55,1570.87 2169.29,1570.87 2389.76,1791.34 2389.76,2125.98 2496.06,2232.28 2496.06,2263.78 2480.31,2279.53 2480.31,2303.15 2468.5,2314.96 2468.5,2649.61 2496.06,2677.17 2496.06,2700.79 2468.5,2728.35 2468.5,2822.83 2547.24,2901.57 2547.24,3086.61 2500,3133.86 2429.13,3133.86 v1(2409.45,3153.54) 2440.94,3185.04 2830.71,3185.04 2850.39,3204.72 2929.72,3204.72 3000,3275 v1(3000,3377.95)
  MidLayer4 w5: v2(1456.69,3381.89) 1456.69,3500 1437.01,3519.68 1437.01,3535.43 1496.06,3594.49 1952.75,3594.49 2023.62,3523.63 v2(2023.62,3503.93) ; v1(2271.65,3500) 2271.65,3519.69 2401.57,3649.61 2937.39,3649.61 3000,3587 v1(3000,3377.95)
  Bottom Layer w5: v2(1456.69,3381.89) U8.23@1456.69,3452.76 ; v1(3000,3377.95) U12.1@3000,3452.76
BUS_A3: U3.C2 U4.M19 U7.24 U8.24 U11.2 U12.2 | length 5554.6
  Top Layer w5: U7.24@2055.12,3452.76 v2(2055.11,3527.55) ; U11.2@2303.15,3452.76 v1(2303.15,3523.62) ; U3.C2@2429.13,3134.84 2430.12,3134.85 v1(2448.82,3153.54)
  Top Layer w7.87: U4.M19@1740.16,1531.5 v1(1759.84,1551.18)
  MidLayer1 w5: v2(2055.11,3527.55) 2055.12,3507.87 2094.49,3468.5 2283.46,3468.5 2303.15,3488.19 v1(2303.15,3523.62)
  MidLayer2 w5: v1(1759.84,1551.18) 1779.53,1531.5 2082.68,1531.5 2094.49,1531.5 2145.67,1531.5 2401.57,1787.4 2401.57,2118.11 2519.68,2236.22 2519.68,2263.78 2527.56,2271.65 2527.56,2287.4 2480.31,2334.65 2480.31,2645.67 2507.87,2673.23 2507.87,2704.72 2480.31,2732.28 2480.31,2755.91 ; 2480.31,2744.09 2480.31,2818.9 2562.99,2901.57 2562.99,3090.55 2500,3153.54 v1(2448.82,3153.54) 2448.82,3169.29 2452.76,3173.23 2838.58,3173.23 2854.33,3188.98 2931.85,3188.98 2953.81,3210.94 2960.94,3210.94 2997.73,3247.73 2997.73,3254.85 3019.68,3276.81 3019.68,3385.83 3003.94,3401.57 v1(2968.5,3401.57)
  MidLayer4 w5: v2(1425.2,3405.51) 1425.2,3472.44 1405.51,3492.13 1405.51,3511.81 1417.32,3523.62 1417.32,3535.43 1488.19,3606.3 1976.37,3606.3 v2(2055.11,3527.55) ; v1(2303.15,3523.62) 2307.09,3523.62 2421.26,3637.8 2932.21,3637.79 2987,3583 2987,3420.07 v1(2968.5,3401.57)
  Bottom Layer w5: v2(1425.2,3405.51) U8.24@1425.2,3452.76 ; v1(2968.5,3401.57) U12.2@2968.5,3452.76
BUS_A4: U3.A2 U4.N25 U7.25 U8.25 U11.3 U12.3 | length 4895.1
  Top Layer w5: U4.N25@1976.38,1492.13 1996.06,1511.81 2031.5,1511.81 2035.43,1507.87 2078.74,1507.87 2094.49,1507.87 2208.66,1507.87 2322.83,1622.05 2322.83,2000 2519.68,2196.85 2519.68,2263.78 2527.56,2271.65 2527.56,2633.86 2547.24,2653.54 2547.24,2763.78 ; U7.25@2086.61,3452.76 v2(2086.61,3503.93) ; U11.3@2334.64,3452.76 v1(2334.64,3500) ; U3.A2@2507.87,3134.84 2550.19,3134.85 ; 2547.24,2748.03 2547.24,2807.09 2606.3,2866.14 2606.3,3078.74 2550.19,3134.85 ; v1(2550.19,3152.55) 2550.19,3134.85
  MidLayer1 w5: v1(2550.19,3152.55) 2719.48,3152.55 2773.86,3206.94 2773.86,3226.62 2862.94,3315.7 2882.63,3315.7 v1(2937.01,3370.08)
  MidLayer4 w5: v2(1393.7,3527.56) 1484.25,3618.11 1992.62,3618.11 2086.61,3524.12 v2(2086.61,3503.93) 2110.23,3480.32 2314.96,3480.32 v1(2334.64,3500) 2334.64,3535.43 2425.19,3625.98 2923.02,3625.98 2976,3573 2976,3441 2937.01,3402.01 v1(2937.01,3370.08)
  Bottom Layer w5: U8.25@1393.7,3452.76 v2(1393.7,3527.56) ; U12.3@2933.07,3430.12 U12.3@2937.01,3434.05 ; U12.3@2933.07,3452.76 2933.07,3417.32 2937.01,3413.39 v1(2937.01,3370.08)
BUS_A5: U3.B2 U4.M26 U7.26 U8.26 U11.4 U12.4 | length 5009.8
  Top Layer w5: U4.M26@2015.75,1531.5 2043.31,1531.5 2051.18,1523.62 2078.74,1523.62 2094.49,1523.62 2208.66,1523.62 2311.02,1625.98 2311.02,2003.94 2496.06,2188.98 2496.06,2263.78 2488.19,2271.65 2488.19,2610.24 2535.43,2657.48 2535.43,2767.72 ; U7.26@2118.11,3452.76 v2(2118.11,3527.55) ; U11.4@2366.14,3452.76 v1(2366.14,3523.62) ; U3.B2@2468.5,3134.84 2468.51,3133.86 v1(2488.19,3114.17) 2519.69,3114.17 2594.49,3039.37 2594.49,2870.08 2535.43,2811.02 2535.43,2755.91
  MidLayer1 w5: v2(2118.11,3527.55) 2165.34,3480.32 2279.53,3480.32 2291.34,3492.13 2291.34,3507.87 2281.65,3517.56 2281.65,3529.68 2299.21,3547.24 2342.52,3547.24 v1(2366.14,3523.62) ; v1(2488.19,3114.17) 2488.19,3133.86 2527.56,3173.23 2718.98,3173.23 2756.89,3211.14 2756.89,3226.38 2873.03,3342.52 2888.27,3342.52 2913.39,3367.64 v1(2913.39,3401.57)
  MidLayer4 w5: v2(1362.2,3405.51) 1362.2,3472.44 1342.52,3492.13 1342.52,3511.81 1460.63,3629.92 2015.74,3629.92 v2(2118.11,3527.55) ; v1(2366.14,3523.62) 2366.14,3535.43 2433.07,3602.36 2893.7,3602.36 2924.7,3571.36 2924.7,3524.11 2933.07,3515.75 2933.07,3421.26 v1(2913.39,3401.57)
  Bottom Layer w5: v2(1362.2,3405.51) U8.26@1362.2,3452.76 ; U12.4@2905.51,3448.82 U12.4@2901.57,3452.76 2901.57,3413.39 v1(2913.39,3401.57)
BUS_A6: U3.D3 U4.E21 U7.29 U8.29 U11.5 U12.5 | length 4758.2
  Top Layer w5: v2(2118.1,3850.39) U7.29@2118.11,3901.57 ; U11.5@2397.64,3452.76 v1(2397.64,3500)
  Top Layer w7.87: U4.E21@1818.9,1807.09 v1(1838.58,1826.77) ; U3.D3@2389.77,3095.48 v1(2409.45,3114.18)
  MidLayer1 w5: v1(2409.45,3114.18) 2425.2,3114.18 2429.13,3118.11 2429.13,3122.05 2440.94,3133.86 2472.44,3133.86 2523.62,3185.04 2700.79,3185.04 v1(2881.89,3366.14)
  MidLayer2 w5: v1(1838.58,1826.77) 1858.27,1846.46 1858.27,2027.56 1858.27,2039.37 1858.27,2122.05 1921.26,2185.04 2082.68,2185.04 2118.11,2220.47 2118.11,2263.78 2106.3,2275.59 2106.3,2291.34 2122.05,2307.09 2122.05,2645.67 2110.24,2657.48 2110.24,2673.23 2311.02,2874.02 2311.02,3082.68 2322.83,3094.49 2350.39,3094.49 2370.08,3114.18 v1(2409.45,3114.18)
  MidLayer3 w5: v2(2118.1,3850.39) 2118.11,3822.84 2397.64,3543.31 v1(2397.64,3500)
  MidLayer4 w5: v2(1362.2,3948.82) 1362.2,3885.83 1342.52,3866.14 1342.52,3842.52 1460.63,3724.41 2011.81,3724.41 2118.1,3830.7 v2(2118.1,3850.39) ; v1(2397.64,3500) 2397.64,3535.93 2440.45,3578.74 2854.33,3578.74 2866.14,3566.93 2866.14,3555.86 2889.76,3532.24 2889.76,3515.75 2881.89,3507.87 v1(2881.89,3366.14)
  Bottom Layer w5: U8.29@1362.2,3901.57 v2(1362.2,3948.82) ; U12.5@2870.08,3452.76 2870.08,3433.07 2881.89,3421.26 v1(2881.89,3366.14)
BUS_A7: U3.C3 U4.L22 U7.30 U8.30 U11.18 U12.18 | length 4903.8
  Top Layer w5: v2(2086.61,3826.77) U7.30@2086.61,3901.57 ; U11.18@2807.09,3452.76 2807.09,3496.06 2826.77,3515.75 2826.77,3527.56 v1(2846.46,3555.12)
  Top Layer w7.87: U4.L22@1858.27,1570.87 v1(1877.95,1590.55) ; U3.C3@2429.14,3095.48 v1(2448.82,3114.17)
  MidLayer2 w5: v1(1877.95,1590.55) 1897.64,1610.24 2078.74,1610.24 2090.55,1610.24 2110.24,1629.92 2110.24,1653.54 2377.95,1921.26 2377.95,2133.86 2456.69,2212.6 2456.69,2263.78 2468.5,2275.59 2468.5,2295.28 2456.69,2307.09 2456.69,2826.77 2507.87,2877.95 2507.87,3082.68 2496.06,3094.49 2468.5,3094.49 v1(2448.82,3114.17) ; v1(2688.98,3295.28) 2795.28,3401.57 2795.28,3484.25 2826.77,3515.75 2826.77,3535.43 v1(2846.46,3555.12)
  MidLayer3 w5: v2(2086.61,3826.77) 2086.61,3858.26 2098.43,3870.08 2125.98,3870.08 2137.8,3858.27 2137.8,3826.77 2409.45,3555.12 2409.45,3515.75 2460.63,3464.57 v2(2460.63,3401.57)
  MidLayer4 w5: v2(1393.7,3826.77) 1484.25,3736.22 1996.06,3736.22 v2(2086.61,3826.77) ; v2(2460.63,3401.57) 2519.68,3460.63 2771.65,3460.63 2826.77,3515.75 2826.77,3535.43 v1(2846.46,3555.12)
  Bottom Layer w5: v2(1393.7,3826.77) U8.30@1393.7,3901.57 ; v1(2448.82,3114.17) 2559.06,3224.41 2606.3,3224.41 2610.24,3228.35 2629.92,3248.03 2629.92,3263.78 2641.73,3275.59 2657.48,3275.59 2669.29,3287.4 2669.29,3291.34 2673.23,3295.28 v1(2688.98,3295.28) ; v2(2460.63,3401.57) U12.18@2460.63,3452.76 U12.18@2460.63,3472.44
BUS_A8: U3.A3 U4.M25 U7.31 U8.31 U11.19 U12.19 | length 4910.7
  Top Layer w5: U4.M25@1976.38,1531.5 1996.06,1551.18 2043.31,1551.18 2055.12,1539.37 2078.74,1539.37 2094.49,1539.37 2208.66,1539.37 2299.21,1629.92 2299.21,2007.87 2456.69,2165.35 2456.69,2263.78 2464.57,2271.65 2464.57,2602.36 2523.62,2661.42 2523.62,2814.96 2582.68,2874.02 2582.68,3019.68 v1(2527.56,3074.8) ; v2(2055.11,3850.39) U7.31@2055.12,3901.57 ; U11.19@2838.58,3452.76 2838.58,3472.44 2858.27,3492.13 2858.27,3511.81 v1(2870.08,3523.62)
  Top Layer w7.87: U3.A3@2507.88,3095.48 v1(2527.56,3074.8)
  MidLayer2 w5: v1(2688.98,3240.16) 2708.66,3240.16 2826.77,3358.27 2826.77,3366.14 2826.77,3437.01 2870.08,3480.31 v1(2870.08,3523.62)
  MidLayer3 w5: v2(2055.11,3850.39) 2055.11,3818.9 2080.55,3793.46 2123.86,3793.46 2370.08,3547.24 2385.83,3531.5 2385.83,3515.28 2385.36,3515.28 2377.95,3507.87 2377.95,3480.32 2429.13,3429.13 v1(2429.13,3377.95)
  MidLayer4 w5: v2(1425.2,3948.82) 1425.2,3885.83 1421.26,3881.89 1405.51,3866.14 1405.51,3842.52 1417.32,3830.71 1417.32,3822.83 1492.13,3748.03 1976.38,3748.03 2055.11,3826.77 v2(2055.11,3850.39) ; v1(2429.13,3377.95) 2448.82,3358.27 2511.81,3358.27 2594.49,3440.94 2811.02,3440.94 2858.27,3488.19 2858.27,3511.81 v1(2870.08,3523.62)
  Bottom Layer w5: U8.31@1425.2,3901.57 v2(1425.2,3948.82) ; v1(2429.13,3377.95) U12.19@2429.13,3452.76 ; v1(2527.56,3074.8) 2527.56,3094.49 2673.23,3240.16 v1(2688.98,3240.16)
BUS_A9: U3.B6 U4.M24 U7.32 U8.32 U11.20 U12.20 | length 5215.5
  Top Layer w5: v2(2023.62,3826.77) U7.32@2023.62,3901.57 ; U11.20@2870.08,3452.76 2870.08,3496.06 2901.57,3527.56 v1(2901.57,3562.99)
  Top Layer w7.87: U4.M24@1937.01,1531.5 v1(1956.69,1551.18) ; U3.B6@2468.5,2977.36 v1@2488.19,2957.68
  MidLayer1 w5: v1(1956.69,1551.18) 2078.74,1551.18 2090.55,1551.18 2188.98,1551.18 2216.54,1578.74 2216.54,1665.35 2299.21,1748.03 2299.21,2098.43 2457.07,2256.28 2457.07,2263.4 2456.69,2263.78 2468.5,2275.59 2468.5,2322.83 2519.68,2374.02 2519.68,2732.28 ; v1@2488.19,2957.68 2507.87,2938 2507.87,2937.01 2507.88,2889.75 2519.66,2877.98 2519.69,2708.66
  MidLayer3 w5: v2(2023.62,3826.77) 2066.93,3783.46 2102.36,3783.46 2122.05,3763.78 2346.46,3539.37 2346.46,3515.75 2366.14,3496.06 2366.14,3433.07 v2(2397.64,3401.57) ; v1(2822.83,3220.47) 2822.7,3238.32 2814.96,3246.06 2814.96,3277.56 2831.69,3294.29 2831.69,3343.5 2881.89,3393.7 2881.89,3507.87 2901.57,3527.56 ; 2901.57,3527.56 v1(2901.57,3562.99)
  MidLayer4 w5: v2(1456.69,3948.82) 1456.69,3854.33 1437.01,3834.65 1437.01,3818.9 1496.06,3759.84 1956.69,3759.84 v2(2023.62,3826.77) ; v2(2397.64,3401.57) 2397.64,3358.27 2429.13,3326.77 2877.95,3326.77 2905.51,3354.33 2905.51,3377.95 2893.7,3389.76 2893.7,3464.57 2921.26,3492.13 2921.26,3507.87 2913.39,3515.75 2913.39,3551.18 v1(2901.57,3562.99)
  Bottom Layer w5: U8.32@1456.69,3901.57 v2(1456.69,3948.82) ; v2(2397.64,3401.57) U12.20@2397.64,3452.76 ; v1(2488.19,2956.69) 2507.87,2976.38 2555.12,2976.38 2570.87,2992.13 2570.87,3055.12 2731.9,3216.15 2814.68,3216.65 v1@2822.84,3224.91
BUS_A10: U3.A6 U4.K26 U7.33 U8.33 U11.21 U12.21 | length 4806.5
  Top Layer w5: v2(1992.12,3850.39) U7.33@1992.13,3901.57 ; U4.K26@2015.75,1610.24 2078.74,1610.24 2094.49,1610.24 2216.54,1610.24 2263.78,1657.48 2263.78,2019.69 2370.08,2125.98 2370.08,2263.78 2362.2,2271.65 2362.2,2291.34 2429.13,2358.27 2429.13,2614.17 2456.69,2641.73 2456.69,2752.14 ; 2456.69,2740.16 2456.69,2795.27 2547.24,2885.83 2547.24,2937.01 v1(2527.56,2956.69) v1@2527.56,2957.68 ; U11.21@2901.57,3452.76 v1(2901.57,3500)
  Top Layer w7.87: U3.A6@2507.87,2977.36 v1@2527.56,2957.68
  MidLayer2 w5: v1(2835.63,3259.84) 2835.63,3284.45 2901.57,3350.39 2901.57,3381.89 2893.7,3389.76 2893.7,3468.5 2901.57,3476.38 v1(2901.57,3500)
  MidLayer3 w5: v2(1992.12,3850.39) 1992.12,3811.03 2031.5,3771.65 2098.43,3771.65 2322.83,3547.24 2322.83,3515.75 2314.96,3507.87 2314.96,3448.82 2366.14,3397.64 v1(2366.14,3377.95)
  MidLayer4 w5: v2(1488.19,3850.39) 1488.19,3814.96 1531.5,3771.65 1937.01,3771.65 1992.12,3826.77 v2(1992.12,3850.39) ; v1(2366.14,3377.95) 2366.14,3496.06 2385.36,3515.28 2385.83,3515.28 2385.83,3540.11 2436.27,3590.55 2862.2,3590.55 2877.95,3574.8 2877.95,3559.06 2901.57,3535.43 v1(2901.57,3500)
  Bottom Layer w5: v2(1488.19,3850.39) U8.33@1488.19,3901.57 ; v1(2366.14,3377.95) U12.21@2366.14,3452.76 ; v1(2527.56,2956.69) 2562.99,2956.69 2598.43,2992.13 2598.43,3066.93 2732.28,3200.79 2831.69,3200.79 2842.52,3211.61 2842.52,3232.29 2835.63,3239.17 v1(2835.63,3259.84) v1@2836.54,3258.79
BUS_A11: U3.C6 U4.L23 U7.34 U8.34 U11.22 U12.22 | length 5177.6
  Top Layer w5: v2(1960.62,3826.77) U7.34@1960.63,3901.57 ; U11.22@2933.07,3452.76 2933.07,3519.68 v1(2944.88,3531.5)
  Top Layer w7.87: U4.L23@1897.64,1570.87 v1(1917.32,1590.55) ; U3.C6@2429.13,2977.36 v1@2448.82,2957.68
  MidLayer1 w5: v1(1917.32,1590.55) 1937.01,1570.87 2078.74,1570.87 2090.55,1570.87 2192.91,1570.87 2204.72,1582.68 2204.72,1669.29 2287.4,1751.97 2287.4,2102.36 2433.07,2248.03 2433.07,2263.78 2421.26,2275.59 2421.26,2299.21 2507.87,2385.83 2507.87,2870.08 2468.51,2909.44 2468.51,2937.99 v1@2448.82,2957.68
  MidLayer2 w5: v1(2944.88,3531.5) 2944.88,3393.7 2956.69,3381.89 2956.69,3358.27 2952.76,3354.33 2937.01,3338.58 2937.01,3297.24 v1(2964.57,3269.68)
  MidLayer3 w5: v2(1960.62,3826.77) 2027.56,3759.84 2094.49,3759.84 2279.53,3574.8 2279.53,3519.68 2291.34,3507.87 2291.34,3444.88 v2(2334.65,3401.57)
  MidLayer4 w5: v2(1519.68,3948.82) 1519.68,3854.33 1500,3834.65 1500,3818.9 1535.43,3783.46 1917.32,3783.46 v2(1960.62,3826.77) ; v2(2334.65,3401.57) 2334.65,3472.44 2354.33,3492.13 2354.33,3507.87 2346.46,3515.75 2346.46,3531.5 2429.13,3614.17 2897.64,3614.17 2944.88,3566.93 v1(2944.88,3531.5) ; v1(2448.82,2956.69) 2468.5,2976.38 2649.61,2976.38 2858.27,3185.04 2909.45,3185.04 2964.57,3240.16 2964.57,3266.73 v1@2961.61,3269.68
  Bottom Layer w5: U8.34@1519.68,3901.57 v2(1519.68,3948.82) ; v2(2334.65,3401.57) U12.22@2334.65,3452.76
BUS_A12: U3.D6 U4.K24 U7.22 U8.22 U11.23 U12.23 | length 5532.1
  Top Layer w5: U7.22@1992.13,3452.76 v2(1992.12,3527.55) ; v2(2933.07,3850.39) U11.23@2933.07,3901.57
  Top Layer w7.87: U4.K24@1937.01,1610.24 v1(1956.69,1629.92) ; U3.D6@2389.76,2977.36 v1@2409.45,2957.68
  MidLayer1 w5: v1(1956.69,1629.92) 2051.18,1629.92 2078.74,1629.92 2094.49,1629.92 2114.17,1649.61 2145.67,1681.1 2200.79,1681.1 2259.84,1740.16 ; 2204.72,1685.04 2275.59,1755.91 2275.59,2106.3 2393.7,2224.41 2393.7,2263.78 2405.51,2275.59 2405.51,2303.15 2417.32,2314.96 2417.32,2665.35 2433.07,2681.1 2433.07,2696.85 2393.7,2736.22 2393.7,2874.02 2429.14,2909.46 2429.14,2937 v1(2409.45,2956.69) 2409.45,2957.68 v1@2409.94,2957.19
  MidLayer2 w5: v2(1992.12,3527.55) 2023.62,3559.06 2141.73,3559.06 2314.96,3732.28 2314.96,3834.64 2326.77,3846.46 v2(2326.77,3952.76) ; v2(2933.07,3850.39) 2933.07,3610.24 3043.31,3500 3043.31,3240.16 v1(2988.19,3185.04)
  MidLayer4 w5: v2(1488.19,3503.94) 1488.19,3539.37 1531.5,3582.68 1937,3582.68 v2(1992.12,3527.55) ; v2(2326.77,3952.76) 2326.77,3933.07 2334.65,3925.2 2334.65,3854.33 2354.33,3834.65 2354.33,3811.02 2370.08,3795.28 2913.39,3795.28 2933.07,3814.96 v2(2933.07,3850.39) ; v1(2409.45,2956.69) 2429.13,2937.01 2740.16,2937.01 2800,2996.85 2800,3060 2830,3090 2950,3090 2988.19,3128.19 v1(2988.19,3185.04)
  Bottom Layer w5: U8.22@1488.19,3452.76 v2(1488.19,3503.94) ; v2(2326.77,3952.76) 2326.77,3929.13 2334.65,3921.26 U12.23@2334.65,3901.57
BUS_A13: U3.B7 U4.J25 U7.35 U8.35 U11.24 U12.24 | length 5076
  Top Layer w5: v2(1929.13,3850.39) U7.35@1929.13,3901.57 ; U4.J25@1976.38,1649.61 1996.06,1669.29 2078.74,1669.29 2094.49,1669.29 2185.04,1669.29 2240.16,1724.41 2240.16,2027.56 2307.09,2094.49 2307.09,2263.78 2299.21,2271.65 2299.21,2290.85 2405.51,2397.14 2405.51,2622.05 2433.07,2649.61 2433.07,2756.79 ; 2433.07,2740.16 2433.07,2807.09 2488.19,2862.21 2488.19,2918.31 U3.B7@2468.5,2937.99 ; v2(2901.57,3826.77) U11.24@2901.57,3901.57
  MidLayer1 w5: v2(1929.13,3850.39) 1929.13,3913.39 2011.81,3996.06 2322.83,3996.06 v2(2366.14,3952.76)
  MidLayer2 w5: v2(2901.57,3826.77) 2913.39,3814.96 2913.39,3606.3 3031.5,3488.19 3031.5,3259.84 v1(2956.69,3185.04)
  MidLayer4 w5: v2(1551.18,3948.82) 1551.18,3881.89 1531.5,3862.2 1531.5,3842.52 1578.74,3795.28 1897.64,3795.28 1929.13,3826.77 v2(1929.13,3850.39) ; v2(2366.14,3952.76) 2421.26,4007.87 2834.65,4007.87 2858.27,3984.25 2858.27,3968.5 2850.39,3960.63 2850.39,3905.51 2889.76,3866.14 2889.76,3838.58 v2(2901.57,3826.77)
  Bottom Layer w5: U8.35@1551.18,3881.89 U8.35@1551.18,3901.57 v2(1551.18,3948.82) ; U12.24@2366.14,3901.57 v2(2366.14,3952.76) ; v1(2488.19,2917.32) 2507.87,2897.64 2559.06,2897.64 2696.85,3035.43 2815.43,3035.43 2870,3090 2930,3090 2956.69,3116.69 v1(2956.69,3185.04)
BUS_A14: U3.A7 U4.K25 U7.36 U8.36 U11.25 U12.25 | length 4886.2
  Top Layer w5: v2(1897.63,3826.77) U7.36@1897.64,3901.57 ; U4.K25@1976.38,1610.24 1996.06,1629.92 2051.18,1629.92 2062.99,1641.73 2078.74,1641.73 2094.49,1641.73 2102.12,1649.36 2180.86,1649.36 2251.97,1720.47 2251.97,2023.62 2330.71,2102.36 2330.71,2263.78 2338.58,2271.65 2338.58,2299.21 2417.32,2377.95 2417.32,2618.11 2444.88,2645.67 2444.88,2754.47 ; 2444.88,2744.09 2444.88,2799.21 2527.56,2881.89 v1@2527.56,2918.31 ; v2(2870.08,3850.39) U11.25@2870.08,3901.57
  Top Layer w7.87: U3.A7@2507.87,2937.99 v1@2527.56,2918.31
  MidLayer1 w5: v2(1897.63,3826.77) 1897.64,3921.26 1917.32,3940.94 1917.32,3956.69 1909.45,3964.57 1909.45,3980.32 1921.26,3992.13 1988.19,3992.13 2003.94,4007.87 2342.52,4007.87 v2(2397.64,3952.76)
  MidLayer3 w5: v2(2870.08,3850.39) 2881.89,3838.58 2881.89,3814.96 2921.26,3775.59 2921.26,3555.12 2913.39,3547.24 2913.39,3515.75 2921.26,3507.87 2921.26,3444.88 2893.7,3417.32 2893.7,3389.76 2901.57,3381.89 2901.57,3354.33 2873.03,3325.79 2873.03,3313.98 2882.87,3304.13 2906.5,3304.13 2934.06,3276.57 v1(2934.06,3166.34)
  MidLayer4 w5: v2(1582.68,3830.71) 1606.3,3807.09 1877.95,3807.09 v2(1897.63,3826.77) ; v2(2397.64,3952.76) 2440.94,3996.06 2791.34,3996.06 2838.58,3948.82 2838.58,3881.89 v2(2870.08,3850.39)
  Bottom Layer w5: v2(1582.68,3830.71) U8.36@1582.68,3901.57 ; U12.25@2397.64,3901.57 v2(2397.64,3952.76) ; v1(2527.56,2917.32) 2551.18,2917.32 2616.5,2982.65 2616.5,3069.26 2736.22,3188.98 2911.42,3188.98 v1(2934.06,3166.34)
